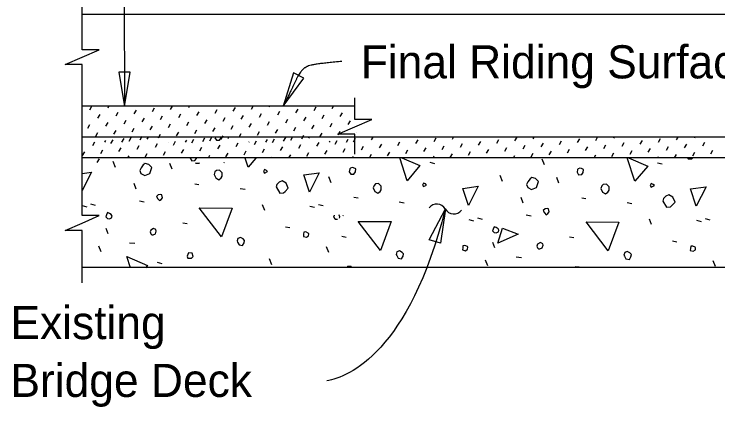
# Model space of a CAD drawing. Extents: x 21526.6 to 21595.9, y 56114.9 to 56157.2.
# Drawn here: x 21526.829 to 21531.109, y 56132.818 to 56135.21 of the extents above; entities that cross this region are included whole.
import ezdxf

# ---------------------------------------------------------------- set-up
doc = ezdxf.new("R2010")
doc.units = 0
for name, color, linetype in [('AdhocPoint_dp', 7, 'Continuous'), ('Border', 7, 'Continuous'), ('Patterning', 7, 'Continuous'), ('PlotBorder_dp', 7, 'Continuous')]:
    doc.layers.add(name, color=color, linetype=linetype)

msp = doc.modelspace()

# ---------------------------------------------------------------- linework, layer by layer
at = {"layer": 'AdhocPoint_dp'}
for p, q in [((21527.2426, 56135.21), (21535.6096, 56135.21)), ((21528.9006, 56134.6484), (21527.2426, 56134.6484)), ((21535.6096, 56134.46), (21527.2426, 56134.46)), ((21535.6096, 56134.335), (21527.2426, 56134.335)), ((21527.2426, 56133.6684), (21535.6096, 56133.6684))]:
    msp.add_line(p, q, dxfattribs=at)
at = {"layer": 'Patterning'}
for p, q in [((21527.2896, 56134.6259), (21527.3025, 56134.6483)), ((21527.4002, 56134.6388), (21527.4057, 56134.6484)), ((21527.449, 56134.59), (21527.462, 56134.6124)), ((21527.5597, 56134.603), (21527.5726, 56134.6254)), ((21527.6703, 56134.6159), (21527.6833, 56134.6383)), ((21527.7809, 56134.6289), (21527.7922, 56134.6484)), ((21527.8916, 56134.6419), (21527.8953, 56134.6484)), ((21527.9404, 56134.593), (21527.9534, 56134.6154)), ((21528.051, 56134.606), (21528.064, 56134.6284)), ((21528.1617, 56134.619), (21528.1746, 56134.6413)), ((21528.2723, 56134.6319), (21528.2818, 56134.6484)), ((21528.3829, 56134.6449), (21528.3849, 56134.6484)), ((21528.4318, 56134.596), (21528.4447, 56134.6184)), ((21528.5424, 56134.609), (21528.5553, 56134.6314)), ((21528.653, 56134.622), (21528.666, 56134.6444)), ((21528.7637, 56134.6349), (21528.7714, 56134.6484)), ((21528.8125, 56134.5861), (21528.8254, 56134.6085)), ((21528.8743, 56134.6479), (21528.8745, 56134.6484)), ((21527.3384, 56134.577), (21527.3514, 56134.5994)), ((21527.6085, 56134.5541), (21527.6215, 56134.5765)), ((21527.7191, 56134.5671), (21527.7321, 56134.5895)), ((21527.8298, 56134.5801), (21527.8427, 56134.6025)), ((21527.9892, 56134.5442), (21528.0022, 56134.5666)), ((21528.0999, 56134.5572), (21528.1128, 56134.5795)), ((21528.2105, 56134.5701), (21528.2235, 56134.5925)), ((21528.3211, 56134.5831), (21528.3341, 56134.6055)), ((21528.4806, 56134.5472), (21528.4936, 56134.5696)), ((21528.5912, 56134.5602), (21528.6042, 56134.5826)), ((21528.7019, 56134.5731), (21528.7148, 56134.5955)), ((21527.2766, 56134.5152), (21527.2896, 56134.5376)), ((21527.3872, 56134.5282), (21527.4002, 56134.5506)), ((21527.4979, 56134.5412), (21527.5108, 56134.5636)), ((21527.6573, 56134.5053), (21527.6703, 56134.5277)), ((21527.768, 56134.5183), (21527.7809, 56134.5407)), ((21527.8786, 56134.5312), (21527.8916, 56134.5536)), ((21528.1487, 56134.5083), (21528.1617, 56134.5307)), ((21528.2593, 56134.5213), (21528.2723, 56134.5437)), ((21528.37, 56134.5342), (21528.3829, 56134.5566)), ((21528.6401, 56134.5113), (21528.653, 56134.5337)), ((21528.7507, 56134.5243), (21528.7637, 56134.5467)), ((21528.8613, 56134.5373), (21528.8743, 56134.5597)), ((21527.3254, 56134.4664), (21527.3384, 56134.4888)), ((21527.4361, 56134.4794), (21527.449, 56134.5018)), ((21527.5467, 56134.4923), (21527.5597, 56134.5147)), ((21527.8168, 56134.4694), (21527.8298, 56134.4918)), ((21527.9274, 56134.4824), (21527.9404, 56134.5048)), ((21528.0381, 56134.4954), (21528.051, 56134.5177)), ((21528.1975, 56134.4595), (21528.2105, 56134.4819)), ((21528.3082, 56134.4724), (21528.3211, 56134.4948)), ((21528.4188, 56134.4854), (21528.4318, 56134.5078)), ((21528.5294, 56134.4984), (21528.5424, 56134.5208)), ((21528.6889, 56134.4625), (21528.7019, 56134.4849)), ((21528.7995, 56134.4755), (21528.8125, 56134.4979)), ((21528.9102, 56134.4884), (21528.9103, 56134.4886)), ((21527.2583, 56134.4585), (21527.2592, 56134.46)), ((21527.3811, 56134.4294), (21527.3872, 56134.44)), ((21527.4178, 56134.4226), (21527.4307, 56134.445)), ((21527.4849, 56134.4305), (21527.4979, 56134.4529)), ((21527.5284, 56134.4356), (21527.5413, 56134.458)), ((21527.5955, 56134.4435), (21527.6085, 56134.4659)), ((21527.639, 56134.4486), (21527.6457, 56134.46)), ((21527.7062, 56134.4565), (21527.7191, 56134.4789)), ((21527.8707, 56134.4294), (21527.8786, 56134.443)), ((21527.9091, 56134.4257), (21527.9221, 56134.4481)), ((21527.9763, 56134.4336), (21527.9892, 56134.4559)), ((21528.0198, 56134.4386), (21528.0321, 56134.46)), ((21528.0869, 56134.4465), (21528.0999, 56134.4689)), ((21528.1304, 56134.4516), (21528.1353, 56134.46)), ((21528.2899, 56134.4157), (21528.3028, 56134.4381)), ((21528.3603, 56134.4294), (21528.37, 56134.446)), ((21528.4005, 56134.4287), (21528.4134, 56134.4511)), ((21528.4676, 56134.4366), (21528.4806, 56134.459)), ((21528.5111, 56134.4416), (21528.5218, 56134.46)), ((21528.5783, 56134.4495), (21528.5912, 56134.4719)), ((21528.6217, 56134.4546), (21528.6249, 56134.46)), ((21528.7812, 56134.4187), (21528.7942, 56134.4411)), ((21528.8499, 56134.4294), (21528.8613, 56134.449)), ((21528.8918, 56134.4317), (21528.9048, 56134.4541)), ((21529.0025, 56134.4447), (21529.0114, 56134.46)), ((21529.1131, 56134.4576), (21529.1145, 56134.46)), ((21529.2726, 56134.4218), (21529.2855, 56134.4441)), ((21529.3832, 56134.4347), (21529.3962, 56134.4571)), ((21529.4938, 56134.4477), (21529.501, 56134.46)), ((21529.7639, 56134.4248), (21529.7769, 56134.4472)), ((21529.8746, 56134.4377), (21529.8875, 56134.46)), ((21529.9852, 56134.4507), (21529.9906, 56134.46)), ((21530.1447, 56134.4148), (21530.1576, 56134.4372)), ((21530.2553, 56134.4278), (21530.2683, 56134.4502)), ((21530.3659, 56134.4408), (21530.3771, 56134.46)), ((21530.4766, 56134.4537), (21530.4802, 56134.46)), ((21530.636, 56134.4179), (21530.649, 56134.4402)), ((21530.7467, 56134.4308), (21530.7596, 56134.4532)), ((21530.8573, 56134.4438), (21530.8667, 56134.46)), ((21530.9679, 56134.4567), (21530.9698, 56134.46)), ((21527.3071, 56134.4097), (21527.3201, 56134.4321)), ((21527.4666, 56134.3738), (21527.4796, 56134.3962)), ((21527.5772, 56134.3868), (21527.5902, 56134.4092)), ((21527.6879, 56134.3997), (21527.7008, 56134.4221)), ((21527.7676, 56134.4294), (21527.768, 56134.43)), ((21527.7985, 56134.4127), (21527.8114, 56134.4351)), ((21527.958, 56134.3768), (21527.9709, 56134.3992)), ((21528.0686, 56134.3898), (21528.0815, 56134.4122)), ((21528.1792, 56134.4028), (21528.1922, 56134.4251)), ((21528.2572, 56134.4294), (21528.2593, 56134.433)), ((21528.4493, 56134.3798), (21528.4623, 56134.4022)), ((21528.56, 56134.3928), (21528.5729, 56134.4152)), ((21528.6706, 56134.4058), (21528.6835, 56134.4282)), ((21528.7468, 56134.4294), (21528.7507, 56134.4361)), ((21528.9407, 56134.3829), (21528.9536, 56134.4053)), ((21529.0513, 56134.3958), (21529.0643, 56134.4182)), ((21529.1619, 56134.4088), (21529.1749, 56134.4312)), ((21529.3214, 56134.3729), (21529.3344, 56134.3953)), ((21529.432, 56134.3859), (21529.445, 56134.4083)), ((21529.5427, 56134.3989), (21529.5556, 56134.4212)), ((21529.6533, 56134.4118), (21529.6663, 56134.4342)), ((21529.8128, 56134.3759), (21529.8257, 56134.3983)), ((21529.9234, 56134.3889), (21529.9364, 56134.4113)), ((21530.034, 56134.4019), (21530.047, 56134.4243)), ((21530.3041, 56134.379), (21530.3171, 56134.4014)), ((21530.4148, 56134.3919), (21530.4277, 56134.4143)), ((21530.5254, 56134.4049), (21530.5384, 56134.4273)), ((21530.7955, 56134.382), (21530.8085, 56134.4044)), ((21530.9061, 56134.3949), (21530.9191, 56134.4173)), ((21531.0168, 56134.4079), (21531.0297, 56134.4303)), ((21527.2453, 56134.3479), (21527.2583, 56134.3703)), ((21527.356, 56134.3608), (21527.3689, 56134.3832)), ((21527.6261, 56134.3379), (21527.639, 56134.3603)), ((21527.7367, 56134.3509), (21527.7497, 56134.3733)), ((21527.8473, 56134.3639), (21527.8603, 56134.3863)), ((21528.1174, 56134.341), (21528.1304, 56134.3633)), ((21528.2281, 56134.3539), (21528.241, 56134.3763)), ((21528.3387, 56134.3669), (21528.3516, 56134.3893)), ((21528.5005, 56134.335), (21528.5111, 56134.3534)), ((21528.6088, 56134.344), (21528.6217, 56134.3664)), ((21528.7194, 56134.3569), (21528.7324, 56134.3793)), ((21528.8301, 56134.3699), (21528.843, 56134.3923)), ((21528.9901, 56134.335), (21529.0025, 56134.3564)), ((21529.1002, 56134.347), (21529.1131, 56134.3694)), ((21529.2108, 56134.36), (21529.2237, 56134.3824)), ((21529.4809, 56134.3371), (21529.4938, 56134.3594)), ((21529.5915, 56134.35), (21529.6045, 56134.3724)), ((21529.7021, 56134.363), (21529.7151, 56134.3854)), ((21529.9722, 56134.3401), (21529.9852, 56134.3625)), ((21530.0829, 56134.353), (21530.0958, 56134.3754)), ((21530.1935, 56134.366), (21530.2065, 56134.3884)), ((21530.3558, 56134.335), (21530.3659, 56134.3525)), ((21530.4636, 56134.3431), (21530.4766, 56134.3655)), ((21530.5742, 56134.3561), (21530.5872, 56134.3784)), ((21530.6849, 56134.369), (21530.6978, 56134.3914)), ((21530.8454, 56134.335), (21530.8573, 56134.3555)), ((21530.955, 56134.3461), (21530.9679, 56134.3685)), ((21531.0656, 56134.3591), (21531.0786, 56134.3815)), ((21527.3349, 56134.3055), (21527.3478, 56134.3279)), ((21527.4465, 56134.2767), (21527.4324, 56134.3121)), ((21527.5212, 56134.335), (21527.5284, 56134.3474)), ((21527.9077, 56134.335), (21527.9091, 56134.3374)), ((21528.0109, 56134.335), (21528.0198, 56134.3504)), ((21528.3974, 56134.335), (21528.4005, 56134.3404)), ((21528.887, 56134.335), (21528.8918, 56134.3435)), ((21529.3766, 56134.335), (21529.3832, 56134.3465)), ((21529.7631, 56134.335), (21529.7639, 56134.3365)), ((21529.8662, 56134.335), (21529.8746, 56134.3495)), ((21530.0545, 56134.292), (21530.0403, 56134.3273)), ((21530.2527, 56134.335), (21530.2553, 56134.3396)), ((21530.7423, 56134.335), (21530.7467, 56134.3426)), ((21527.6176, 56134.3044), (21527.6179, 56134.305)), ((21527.7906, 56134.265), (21527.7765, 56134.3003)), ((21528.1072, 56134.3044), (21528.1093, 56134.308)), ((21529.3562, 56134.3079), (21529.3845, 56134.3008)), ((21530.7409, 56134.3043), (21530.7691, 56134.2973)), ((21529.7981, 56134.1912), (21529.784, 56134.2266)), ((21528.7575, 56134.183), (21528.7434, 56134.2183)), ((21530.1422, 56134.1795), (21530.1281, 56134.2148)), ((21527.572, 56134.1442), (21527.5597, 56134.1777)), ((21527.9285, 56134.1766), (21527.9533, 56134.1731)), ((21528.2043, 56134.1483), (21528.2343, 56134.143)), ((21528.8954, 56134.0946), (21528.9202, 56134.0911)), ((21527.2945, 56134.054), (21527.3228, 56134.0469)), ((21527.5909, 56134.0723), (21527.6209, 56134.067)), ((21529.1712, 56134.0663), (21529.2012, 56134.061)), ((21529.9236, 56134.0586), (21529.9113, 56134.0922)), ((21530.2801, 56134.0911), (21530.3049, 56134.0875)), ((21530.5559, 56134.0628), (21530.5859, 56134.0575)), ((21527.2421, 56134.044), (21527.2704, 56134.037)), ((21528.3528, 56134.014), (21528.3404, 56134.0476)), ((21528.6268, 56134.0405), (21528.6551, 56134.0334)), ((21528.6792, 56134.0505), (21528.7075, 56134.0434)), ((21529.6461, 56133.9685), (21529.6744, 56133.9614)), ((21529.9425, 56133.9868), (21529.9725, 56133.9815)), ((21527.8543, 56133.9397), (21527.8808, 56133.9344)), ((21529.5937, 56133.9585), (21529.622, 56133.9514)), ((21530.7044, 56133.9284), (21530.692, 56133.962)), ((21530.9784, 56133.955), (21531.0067, 56133.9479)), ((21531.0308, 56133.9649), (21531.0591, 56133.9579)), ((21527.4006, 56133.8714), (21527.3882, 56133.905)), ((21528.48, 56133.915), (21528.5066, 56133.9097)), ((21528.8212, 56133.8577), (21528.8477, 56133.8524)), ((21530.2059, 56133.8542), (21530.2324, 56133.8489)), ((21527.3581, 56133.7618), (21527.344, 56133.7972)), ((21527.5308, 56133.8177), (21527.5626, 56133.8142)), ((21529.7522, 56133.7859), (21529.7398, 56133.8195)), ((21530.8316, 56133.8294), (21530.8582, 56133.8241)), ((21528.7428, 56133.7583), (21528.7287, 56133.7936)), ((21528.397, 56133.6834), (21528.3828, 56133.7188)), ((21529.7097, 56133.6763), (21529.6956, 56133.7116)), ((21529.8824, 56133.7322), (21529.9142, 56133.7287)), ((21527.6987, 56133.6993), (21527.727, 56133.6922)), ((21531.0944, 56133.6727), (21531.0803, 56133.7081))]:
    msp.add_line(p, q, dxfattribs=at)
for points in [[(21528.0505, 56134.4567), (21528.0591, 56134.4413), (21528.0785, 56134.443), (21528.0874, 56134.4554), (21528.0875, 56134.4567)], [(21527.9005, 56134.3317), (21527.9091, 56134.3163), (21527.9285, 56134.318), (21527.9373, 56134.3304), (21527.9375, 56134.3317)], [(21528.252, 56134.2774), (21528.2343, 56134.3317)], [(21528.298, 56134.3317), (21528.252, 56134.2774)], [(21529.2189, 56134.1954), (21529.1735, 56134.335)], [(21529.1874, 56134.335), (21529.2967, 56134.2873), (21529.2189, 56134.1954)], [(21530.6036, 56134.1918), (21530.557, 56134.335)], [(21530.564, 56134.335), (21530.6814, 56134.2838), (21530.6036, 56134.1918)], [(21530.9257, 56134.335), (21530.9282, 56134.3291), (21530.9247, 56134.3326)], [(21530.9282, 56134.3291), (21530.9495, 56134.3291), (21530.9554, 56134.335)], [(21527.6003, 56134.2396), (21527.6233, 56134.2272), (21527.6534, 56134.2396), (21527.6657, 56134.2767), (21527.6481, 56134.2944), (21527.6251, 56134.2997), (21527.6145, 56134.2927), (21527.6021, 56134.2732), (21527.5933, 56134.2573), (21527.6003, 56134.2396)], [(21527.9326, 56134.3044), (21527.9336, 56134.302), (21527.9312, 56134.3044)], [(21527.9336, 56134.302), (21527.9548, 56134.302), (21527.9572, 56134.3044)], [(21528.8671, 56134.2502), (21528.876, 56134.2343), (21528.8954, 56134.236), (21528.9043, 56134.2484), (21528.906, 56134.2678), (21528.8937, 56134.2731), (21528.8848, 56134.2749), (21528.8742, 56134.2714), (21528.8707, 56134.2678), (21528.8671, 56134.2502)], [(21530.2518, 56134.2466), (21530.2607, 56134.2307), (21530.2801, 56134.2325), (21530.2889, 56134.2449), (21530.2907, 56134.2643), (21530.2783, 56134.2696), (21530.2695, 56134.2714), (21530.2589, 56134.2678), (21530.2554, 56134.2643), (21530.2518, 56134.2466)], [(21527.2426, 56134.2391), (21527.2998, 56134.2467), (21527.2427, 56134.1358)], [(21528.0452, 56134.2332), (21528.0558, 56134.212), (21528.0735, 56134.2014), (21528.0876, 56134.212), (21528.0947, 56134.2226), (21528.0947, 56134.2438), (21528.0788, 56134.2597), (21528.0593, 56134.2579), (21528.0505, 56134.2491), (21528.0452, 56134.2332)], [(21528.351, 56134.242), (21528.3704, 56134.2509), (21528.3634, 56134.2579), (21528.351, 56134.2632), (21528.3457, 56134.2509), (21528.351, 56134.242)], [(21528.6244, 56134.1265), (21528.5908, 56134.2308), (21528.6845, 56134.2432), (21528.6244, 56134.1265)], [(21528.4217, 56134.1572), (21528.4447, 56134.12), (21528.4677, 56134.1218), (21528.4765, 56134.1306), (21528.496, 56134.1501), (21528.4836, 56134.1801), (21528.4588, 56134.1943), (21528.4412, 56134.1872), (21528.427, 56134.1731), (21528.4217, 56134.1572)], [(21529.3179, 56134.16), (21529.3374, 56134.1689), (21529.3303, 56134.1759), (21529.3179, 56134.1812), (21529.3126, 56134.1689), (21529.3179, 56134.16)], [(21529.9519, 56134.1541), (21529.9749, 56134.1417), (21530.005, 56134.1541), (21530.0173, 56134.1912), (21529.9997, 56134.2089), (21529.9767, 56134.2142), (21529.9661, 56134.2071), (21529.9537, 56134.1877), (21529.9449, 56134.1718), (21529.9519, 56134.1541)], [(21529.0121, 56134.1512), (21529.0227, 56134.13), (21529.0404, 56134.1194), (21529.0545, 56134.13), (21529.0616, 56134.1406), (21529.0616, 56134.1618), (21529.0457, 56134.1777), (21529.0262, 56134.1759), (21529.0174, 56134.1671), (21529.0121, 56134.1512)], [(21529.5913, 56134.0445), (21529.5577, 56134.1488), (21529.6514, 56134.1612), (21529.5913, 56134.0445)], [(21530.3968, 56134.1476), (21530.4074, 56134.1264), (21530.4251, 56134.1158), (21530.4392, 56134.1264), (21530.4463, 56134.137), (21530.4463, 56134.1582), (21530.4304, 56134.1742), (21530.4109, 56134.1724), (21530.4021, 56134.1635), (21530.3968, 56134.1476)], [(21530.7026, 56134.1565), (21530.722, 56134.1653), (21530.715, 56134.1724), (21530.7026, 56134.1777), (21530.6973, 56134.1653), (21530.7026, 56134.1565)], [(21530.976, 56134.0409), (21530.9424, 56134.1452), (21531.0361, 56134.1576), (21530.976, 56134.0409)], [(21527.7022, 56134.0847), (21527.7128, 56134.0741), (21527.7234, 56134.0811), (21527.7305, 56134.0918), (21527.727, 56134.1094), (21527.7181, 56134.1112), (21527.7058, 56134.1094), (21527.6952, 56134.0988), (21527.7022, 56134.0847)], [(21530.7733, 56134.0716), (21530.7963, 56134.0345), (21530.8193, 56134.0363), (21530.8281, 56134.0451), (21530.8476, 56134.0646), (21530.8352, 56134.0946), (21530.8104, 56134.1087), (21530.7928, 56134.1017), (21530.7786, 56134.0875), (21530.7733, 56134.0716)], [(21528.0894, 56133.8531), (21527.955, 56134.0299), (21528.1548, 56134.0281), (21528.0894, 56133.8531)], [(21530.0538, 56133.9991), (21530.0644, 56133.9885), (21530.075, 56133.9956), (21530.0821, 56134.0062), (21530.0786, 56134.0239), (21530.0697, 56134.0257), (21530.0574, 56134.0239), (21530.0468, 56134.0133), (21530.0538, 56133.9991)], [(21527.397, 56133.9656), (21527.4094, 56133.9638), (21527.4218, 56133.9692), (21527.4253, 56133.9798), (21527.42, 56133.9886), (21527.4094, 56133.9957), (21527.397, 56134.001), (21527.39, 56133.9868), (21527.3864, 56133.9762), (21527.397, 56133.9656)], [(21528.776, 56133.9861), (21528.7746, 56133.9833), (21528.7711, 56133.9727), (21528.7817, 56133.9621)], [(21528.8073, 56133.9681), (21528.81, 56133.9762), (21528.8047, 56133.9851), (21528.8031, 56133.9861)], [(21528.8302, 56133.9823), (21528.8314, 56133.9861)], [(21528.7817, 56133.9621), (21528.7941, 56133.9603), (21528.796, 56133.9611)], [(21529.0563, 56133.7711), (21528.9219, 56133.9479), (21529.1217, 56133.9461), (21529.0563, 56133.7711)], [(21530.441, 56133.7676), (21530.3066, 56133.9443), (21530.5064, 56133.9426), (21530.441, 56133.7676)], [(21527.6669, 56133.8655), (21527.6739, 56133.8655), (21527.6881, 56133.8725), (21527.6934, 56133.8885), (21527.6916, 56133.8973), (21527.6775, 56133.9044), (21527.6598, 56133.8938), (21527.6563, 56133.8832), (21527.6598, 56133.8725), (21527.6669, 56133.8655)], [(21528.5879, 56133.8566), (21528.6073, 56133.8513), (21528.6197, 56133.8602), (21528.6215, 56133.8725), (21528.6179, 56133.8761), (21528.6038, 56133.8832), (21528.5914, 56133.8814), (21528.5897, 56133.869), (21528.5879, 56133.8566)], [(21529.7486, 56133.8801), (21529.761, 56133.8783), (21529.7734, 56133.8836), (21529.7769, 56133.8942), (21529.7716, 56133.9031), (21529.761, 56133.9101), (21529.7486, 56133.9154), (21529.7416, 56133.9013), (21529.738, 56133.8907), (21529.7486, 56133.8801)], [(21529.771, 56133.8153), (21529.7993, 56133.9072), (21529.893, 56133.8701), (21529.771, 56133.8153)], [(21528.1884, 56133.8213), (21528.1972, 56133.8054), (21528.2184, 56133.8018), (21528.2273, 56133.8177), (21528.2308, 56133.8319), (21528.222, 56133.8407), (21528.206, 56133.8496), (21528.1901, 56133.8443), (21528.1848, 56133.8284), (21528.1884, 56133.8213)], [(21529.5548, 56133.7746), (21529.5742, 56133.7693), (21529.5866, 56133.7782), (21529.5884, 56133.7905), (21529.5849, 56133.7941), (21529.5707, 56133.8012), (21529.5583, 56133.7994), (21529.5566, 56133.787), (21529.5548, 56133.7746)], [(21530.0185, 56133.7799), (21530.0255, 56133.7799), (21530.0397, 56133.787), (21530.045, 56133.8029), (21530.0432, 56133.8118), (21530.0291, 56133.8188), (21530.0114, 56133.8082), (21530.0079, 56133.7976), (21530.0114, 56133.787), (21530.0185, 56133.7799)], [(21530.9395, 56133.7711), (21530.9589, 56133.7658), (21530.9713, 56133.7746), (21530.9731, 56133.787), (21530.9695, 56133.7905), (21530.9554, 56133.7976), (21530.943, 56133.7959), (21530.9412, 56133.7835), (21530.9395, 56133.7711)], [(21527.8861, 56133.7241), (21527.9073, 56133.7241), (21527.9179, 56133.7347), (21527.9126, 56133.7541), (21527.8896, 56133.7559), (21527.8861, 56133.7453), (21527.8808, 56133.7364), (21527.8861, 56133.7241), (21527.8825, 56133.7276)], [(21529.1553, 56133.7393), (21529.1641, 56133.7234), (21529.1853, 56133.7198), (21529.1942, 56133.7357), (21529.1977, 56133.7499), (21529.1889, 56133.7587), (21529.173, 56133.7676), (21529.1571, 56133.7623), (21529.1518, 56133.7464), (21529.1553, 56133.7393)], [(21530.54, 56133.7357), (21530.5488, 56133.7198), (21530.57, 56133.7163), (21530.5789, 56133.7322), (21530.5824, 56133.7464), (21530.5736, 56133.7552), (21530.5576, 56133.764), (21530.5417, 56133.7587), (21530.5364, 56133.7428), (21530.54, 56133.7357)], [(21527.536, 56133.665), (21527.5137, 56133.7335), (21527.6392, 56133.6787), (21527.6276, 56133.665)], [(21528.8805, 56133.6684), (21528.8795, 56133.6721), (21528.8565, 56133.6739), (21528.8547, 56133.6684)], [(21530.2643, 56133.6684), (21530.2642, 56133.6686), (21530.2412, 56133.6703), (21530.2406, 56133.6684)]]:
    msp.add_lwpolyline(points, dxfattribs=at)
at = {"layer": 'PlotBorder_dp'}
for points in [[(21527.2427, 56134.3351), (21527.2427, 56134.9021), (21527.1393, 56134.9021), (21527.2427, 56134.9471), (21527.346, 56134.9921), (21527.2427, 56134.9921), (21527.2427, 56135.3182)], [(21528.9006, 56134.3576), (21528.9006, 56134.4784), (21528.7973, 56134.4784), (21528.9006, 56134.5234), (21529.004, 56134.5684), (21528.9006, 56134.5684), (21528.9006, 56134.699)], [(21527.2427, 56133.5727), (21527.2427, 56133.8927), (21527.1393, 56133.8927), (21527.2427, 56133.9377), (21527.346, 56133.9827), (21527.2427, 56133.9827), (21527.2427, 56134.3351)]]:
    msp.add_lwpolyline(points, dxfattribs=at)
for points in [[(21527.5005, 56134.6471), (21527.5357, 56134.8553), (21527.4652, 56134.8553)], [(21528.466, 56134.6497), (21528.5907, 56134.8202), (21528.5275, 56134.8517)], [(21529.4513, 56134.0231), (21529.4208, 56133.8141), (21529.3537, 56133.8358)]]:
    msp.add_lwpolyline(points, close=True, dxfattribs=at)
for centre, start, end in [((21529.3989, 56133.9934), 30.0081, 141.7354), ((21529.5022, 56134.053), 210.0081, 321.7354)]:
    msp.add_arc(centre, 0.0596, start, end, dxfattribs=at)
for points, degree in [([(21527.3644, 56139.6956), (21527.0208, 56139.6041), (21527.2362, 56139.0828), (21527.253, 56138.6974), (21527.5005, 56137.7639), (21527.5005, 56134.6471)], 2), ([(21528.8223, 56134.922), (21528.6486, 56134.9066), (21528.5744, 56134.8752), (21528.5088, 56134.7353), (21528.466, 56134.6497)], 2), ([(21529.4505, 56134.0233), (21529.2298, 56133.1495), (21528.8654, 56133.0028), (21528.7303, 56132.976)], 3)]:
    msp.add_open_spline(points, degree=degree, dxfattribs=at)

# ---------------------------------------------------------------- texts
at = {"layer": 'Border'}
msp.add_text('Final Riding Surface', height=0.2016, dxfattribs=at).set_placement((21528.9369, 56134.8183))
at = {"layer": 'PlotBorder_dp'}
for s, p in [('Existing ', (21526.8068, 56133.2307)), ('Bridge Deck', (21526.8068, 56132.8787))]:
    msp.add_text(s, height=0.2016, dxfattribs=at).set_placement(p)

doc.saveas('drawing.dxf')
